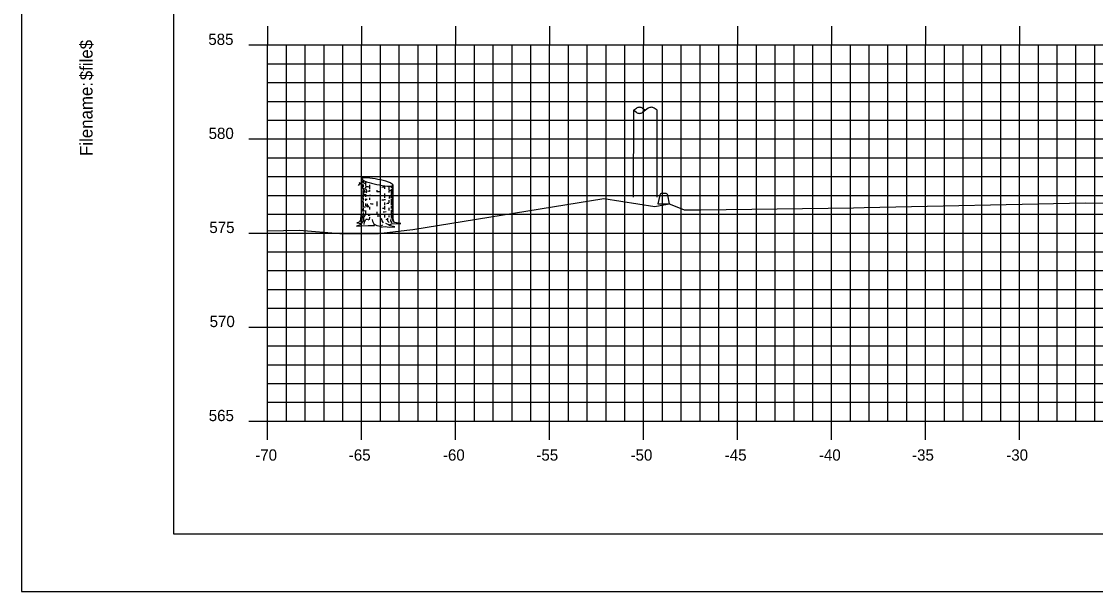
# Model space of a CAD drawing. Extents: x 1048343 to 1048513, y 781387 to 781497.
# Drawn here: x 1048343 to 1048400.2, y 781387.3 to 781417.6 of the extents above; entities that cross this region are included whole.
import ezdxf

# ---------------------------------------------------------------- set-up
doc = ezdxf.new("R2010")
doc.units = 0
for name, color, linetype in [('BORDER', 7, 'Continuous'), ('H_V ANNOTATION', 7, 'Continuous'), ('M_Trees_Conifer_Pay', 7, 'Continuous'), ('MAJOR', 7, 'Continuous'), ('MINOR', 7, 'Continuous'), ('PLOT BOUNDARY', 7, 'Continuous'), ('S_Curb_Type_3', 7, 'Continuous'), ('S_Roadway_Centerline', 7, 'Continuous'), ('S_Utilities_Pole_Power', 7, 'Continuous')]:
    doc.layers.add(name, color=color, linetype=linetype)

msp = doc.modelspace()

# ---------------------------------------------------------------- linework, layer by layer
at = {"layer": 'BORDER'}
msp.add_lwpolyline([(1048351.12, 781390.375), (1048511.12, 781390.375), (1048511.12, 781495.375), (1048351.12, 781495.375)], close=True, dxfattribs=at)
at = {"layer": 'M_Trees_Conifer_Pay'}
for p, q in [((1048361.128, 781407.614), (1048361.128, 781409.261)), ((1048361.2, 781409.188), (1048361.2, 781409.026)), ((1048361.2, 781408.958), (1048361.2, 781408.83)), ((1048361.317, 781409.127), (1048361.317, 781408.904)), ((1048361.317, 781408.816), (1048361.317, 781408.768)), ((1048361.546, 781408.931), (1048361.546, 781408.732)), ((1048362.342, 781408.889), (1048362.342, 781408.721)), ((1048362.562, 781408.869), (1048362.562, 781408.637)), ((1048362.687, 781408.877), (1048362.687, 781408.779)), ((1048362.745, 781408.888), (1048362.745, 781408.417)), ((1048362.792, 781407.203), (1048362.792, 781408.925)), ((1048361.2, 781408.643), (1048361.2, 781408.307)), ((1048361.2, 781408.27), (1048361.2, 781408.108)), ((1048361.26, 781408.633), (1048361.312, 781408.573)), ((1048361.317, 781408.433), (1048361.317, 781408.301)), ((1048361.317, 781408.19), (1048361.317, 781408.081)), ((1048361.546, 781408.674), (1048361.546, 781408.585)), ((1048361.546, 781408.238), (1048361.546, 781408.133)), ((1048361.936, 781408.658), (1048361.936, 781408.562)), ((1048362.342, 781408.484), (1048362.342, 781408.247)), ((1048362.562, 781408.596), (1048362.562, 781408.522)), ((1048362.687, 781408.705), (1048362.687, 781408.501)), ((1048362.687, 781408.443), (1048362.687, 781408.244)), ((1048362.687, 781408.196), (1048362.687, 781407.86)), ((1048362.745, 781408.352), (1048362.745, 781408.044)), ((1048361.2, 781408.06), (1048361.2, 781407.844)), ((1048361.2, 781407.813), (1048361.2, 781407.739)), ((1048361.2, 781407.698), (1048361.2, 781407.525)), ((1048361.317, 781407.945), (1048361.317, 781407.803)), ((1048361.546, 781407.766), (1048361.546, 781407.619)), ((1048361.936, 781408.044), (1048361.936, 781407.97)), ((1048361.936, 781407.945), (1048361.936, 781407.797)), ((1048362.342, 781408.003), (1048362.342, 781407.85)), ((1048362.342, 781407.807), (1048362.342, 781407.634)), ((1048362.562, 781408.118), (1048362.562, 781407.98)), ((1048362.562, 781407.708), (1048362.562, 781407.566)), ((1048362.687, 781407.807), (1048362.687, 781407.671)), ((1048362.745, 781407.997), (1048362.745, 781407.505)), ((1048361.317, 781407.576), (1048361.317, 781407.404)), ((1048361.546, 781407.387), (1048361.546, 781407.299)), ((1048361.936, 781407.505), (1048361.936, 781407.352)), ((1048362.342, 781407.356), (1048362.342, 781407.203)), ((1048362.562, 781407.305), (1048362.562, 781407.21)), ((1048362.687, 781407.572), (1048362.687, 781407.194)), ((1048362.745, 781407.451), (1048362.745, 781407.203)), ((1048362.124, 781406.746), (1048362.25, 781406.81)), ((1048362.562, 781406.81), (1048362.399, 781406.874))]:
    msp.add_line(p, q, dxfattribs=at)
for points in [[(1048361.083, 781408.992), (1048361.007, 781408.999), (1048360.935, 781408.9)], [(1048361.312, 781408.759), (1048361.275, 781408.684), (1048361.228, 781408.742), (1048361.17, 781408.81), (1048361.077, 781409.003), (1048361.013, 781409.051), (1048360.982, 781409.057)], [(1048361.297, 781408.505), (1048361.26, 781408.633), (1048361.197, 781408.748), (1048361.166, 781408.816), (1048361.097, 781408.962)], [(1048361.345, 781408.721), (1048361.376, 781408.637), (1048361.38, 781408.569), (1048361.349, 781408.505)], [(1048362.613, 781408.231), (1048362.619, 781408.326), (1048362.576, 781408.303), (1048362.576, 781408.209)], [(1048361.128, 781407.614), (1048361.077, 781407.352), (1048361.061, 781407.078), (1048361.003, 781406.953), (1048360.867, 781406.922), (1048361.098, 781406.885), (1048361.098, 781406.885), (1048361.092, 781406.837), (1048360.844, 781406.743), (1048361.119, 781406.759), (1048361.474, 781406.78), (1048361.796, 781406.769), (1048361.789, 781406.852), (1048361.937, 781406.769), (1048362.124, 781406.746), (1048362.1, 781406.679), (1048362.368, 781406.722), (1048362.588, 781406.695), (1048362.881, 781406.712), (1048362.592, 781406.769), (1048362.562, 781406.81), (1048362.724, 781406.868), (1048362.961, 781406.879), (1048363.202, 781406.879), (1048362.86, 781406.936), (1048362.819, 781407.016), (1048362.792, 781407.203)], [(1048361.474, 781407.832), (1048361.462, 781407.755), (1048361.415, 781407.766), (1048361.427, 781407.932)], [(1048361.302, 781407.326), (1048361.228, 781407.221), (1048361.223, 781407.047), (1048361.098, 781406.885)], [(1048361.203, 781407.471), (1048361.197, 781407.326), (1048361.149, 781407.257), (1048361.139, 781407.058)], [(1048361.26, 781406.831), (1048361.275, 781406.969), (1048361.349, 781407.098)], [(1048361.539, 781407.221), (1048361.528, 781407.095), (1048361.454, 781407.051)], [(1048361.789, 781406.852), (1048361.715, 781406.994), (1048361.705, 781407.095)], [(1048362.277, 781406.922), (1048362.21, 781407.016), (1048362.183, 781407.156)], [(1048362.504, 781407.163), (1048362.504, 781407.031), (1048362.592, 781406.932)], [(1048362.666, 781407.136), (1048362.661, 781407.02), (1048362.714, 781406.932), (1048362.724, 781406.868)], [(1048362.745, 781407.156), (1048362.766, 781407.078), (1048362.786, 781406.984)]]:
    msp.add_lwpolyline(points, dxfattribs=at)
for centre, radius, start, end in [((1048361.151, 781409.261), 0.0226, 168.2806, 179.9685), ((1048361.155, 781409.261), 0.0264, 179.9685, 190.7806), ((1048361.162, 781409.134), 0.0334, 185.7849, 196.0515), ((1048361.162, 781408.98), 0.0334, 185.7849, 196.0515), ((1048361.151, 781409.261), 0.0226, 156.5926, 168.2806), ((1048361.16, 781409.262), 0.0314, 190.7806, 203.4842), ((1048361.172, 781409.137), 0.0441, 196.0515, 210), ((1048361.172, 781408.983), 0.0441, 196.0515, 210), ((1048361.154, 781409.259), 0.0264, 145.7806, 156.5926), ((1048361.179, 781409.27), 0.0527, 203.4842, 213.2806), ((1048361.159, 781409.256), 0.0314, 133.077, 145.7806), ((1048361.188, 781409.146), 0.0624, 210, 228.7494), ((1048361.188, 781408.992), 0.0624, 210, 228.7494), ((1048361.203, 781409.286), 0.0817, 213.2806, 227.6113), ((1048361.173, 781409.241), 0.0527, 123.2806, 133.077), ((1048361.189, 781409.217), 0.0817, 108.9499, 123.2806), ((1048361.26, 781409.229), 0.172, 228.7494, 240), ((1048361.26, 781409.075), 0.172, 228.7494, 240), ((1048361.317, 781409.411), 0.251, 227.6113, 235.7806), ((1048361.244, 781409.057), 0.251, 100.7806, 108.9499), ((1048361.459, 781409.42), 0.571, 240, 242.9763), ((1048361.627, 781409.866), 0.802, 235.7806, 251.9406), ((1048361.347, 781408.516), 0.802, 84.6206, 100.7806), ((1048361.459, 781409.574), 0.571, 247.5868, 255.5683), ((1048361.459, 781409.42), 0.571, 255.6333, 261.8968), ((1048362.984, 781414.028), 5.179, 251.9406, 258.2806), ((1048361.96, 781412.937), 4.124, 261.8968, 263.762), ((1048360.937, 781404.158), 5.179, 78.2806, 84.6206), ((1048362.984, 781414.028), 5.179, 258.2806, 264.6206), ((1048360.937, 781404.158), 5.179, 71.9406, 78.2806), ((1048361.96, 781412.937), 4.124, 273.2669, 275.3045), ((1048362.574, 781409.67), 0.802, 264.6206, 280.7806), ((1048362.294, 781408.319), 0.802, 55.7806, 71.9406), ((1048362.677, 781409.129), 0.251, 280.7806, 288.9499), ((1048362.603, 781408.775), 0.251, 47.6113, 55.7806), ((1048362.732, 781408.969), 0.0817, 288.9499, 303.2806), ((1048362.717, 781408.9), 0.0817, 33.2806, 47.6113), ((1048362.748, 781408.945), 0.0527, 303.2806, 313.077), ((1048362.762, 781408.929), 0.0314, 313.077, 325.7806), ((1048362.741, 781408.916), 0.0527, 23.4842, 33.2806), ((1048362.766, 781408.926), 0.0264, 325.7806, 336.5926), ((1048362.761, 781408.924), 0.0314, 10.7806, 23.4842), ((1048362.77, 781408.925), 0.0226, 336.5926, 348.2806), ((1048362.766, 781408.925), 0.0264, 359.9685, 10.7806), ((1048362.77, 781408.925), 0.0226, 348.2806, 359.9685), ((1048362.76, 781408.747), 0.0334, 0, 16.0515), ((1048361.162, 781408.536), 0.0334, 185.7849, 196.0515), ((1048361.163, 781408.3), 0.0334, 185.7849, 196.0515), ((1048361.173, 781408.303), 0.0441, 196.0515, 210), ((1048361.189, 781408.312), 0.0624, 210, 228.7494), ((1048361.262, 781408.395), 0.172, 228.7494, 240), ((1048361.461, 781408.74), 0.571, 240, 242.8104), ((1048361.46, 781408.976), 0.571, 242.9571, 255.5507), ((1048361.461, 781408.74), 0.571, 253.0704, 261.8968), ((1048361.962, 781412.704), 4.124, 262.9442, 264.2151), ((1048361.96, 781412.493), 4.124, 264.0496, 266.2948), ((1048361.962, 781412.704), 4.124, 269.6419, 270), ((1048361.962, 781412.704), 4.124, 270, 271.9249), ((1048362.462, 781409.187), 0.571, 282.0154, 293.1403), ((1048362.461, 781408.976), 0.571, 292.9413, 300), ((1048362.462, 781409.187), 0.571, 299.6633, 300), ((1048362.462, 781408.74), 0.571, 299.6633, 300), ((1048362.662, 781408.842), 0.172, 300, 311.2506), ((1048362.662, 781408.395), 0.172, 300, 311.2506), ((1048362.734, 781408.759), 0.0624, 311.2506, 330), ((1048362.734, 781408.312), 0.0624, 311.2506, 330), ((1048362.75, 781408.75), 0.0441, 330, 343.9485), ((1048362.75, 781408.303), 0.0441, 330, 343.9485), ((1048362.76, 781408.747), 0.0334, 343.9485, 360), ((1048362.76, 781408.3), 0.0334, 0, 16.0515), ((1048362.76, 781408.3), 0.0334, 343.9485, 360), ((1048361.163, 781408.09), 0.0334, 185.7849, 196.0515), ((1048361.163, 781407.656), 0.0334, 185.7849, 196.0515), ((1048361.173, 781408.093), 0.0441, 196.0515, 210), ((1048361.173, 781407.659), 0.0441, 196.0515, 210), ((1048361.189, 781408.102), 0.0624, 210, 228.7494), ((1048361.189, 781407.668), 0.0624, 210, 228.7494), ((1048361.262, 781408.185), 0.172, 228.7494, 240), ((1048361.262, 781407.75), 0.172, 228.7494, 240), ((1048361.461, 781408.53), 0.571, 240, 242.8104), ((1048361.461, 781408.293), 0.571, 242.8104, 254.6017), ((1048361.962, 781412.258), 4.124, 261.8968, 262.3875), ((1048361.962, 781412.048), 4.124, 264.5431, 266.8507), ((1048361.962, 781412.048), 4.124, 269.6419, 270), ((1048361.962, 781412.258), 4.124, 273.3324, 275.919), ((1048361.962, 781411.811), 4.124, 273.6807, 275.284), ((1048361.962, 781412.048), 4.124, 276.8526, 278.1032), ((1048362.462, 781408.53), 0.571, 278.1032, 280.7293), ((1048362.462, 781408.53), 0.571, 293.1403, 300), ((1048362.462, 781408.293), 0.571, 293.1403, 300), ((1048362.662, 781408.185), 0.172, 300, 311.2506), ((1048362.662, 781407.948), 0.172, 300, 311.2506), ((1048362.734, 781408.102), 0.0624, 311.2506, 330), ((1048362.734, 781407.866), 0.0624, 311.2506, 330), ((1048362.75, 781408.093), 0.0441, 330, 343.9485), ((1048362.75, 781407.856), 0.0441, 330, 343.9485), ((1048362.76, 781408.09), 0.0334, 0, 16.0515), ((1048362.76, 781408.09), 0.0334, 343.9485, 360), ((1048362.76, 781407.853), 0.0334, 0, 16.0515), ((1048362.76, 781407.853), 0.0334, 343.9485, 360), ((1048362.76, 781407.656), 0.0334, 0, 16.0515), ((1048361.163, 781407.24), 0.0334, 185.7849, 196.0515), ((1048361.173, 781407.243), 0.0441, 196.0515, 210), ((1048361.189, 781407.252), 0.0624, 210, 228.7494), ((1048361.262, 781407.335), 0.172, 228.7494, 240), ((1048361.461, 781408.096), 0.571, 240, 250.7093), ((1048361.461, 781407.9), 0.571, 242.7279, 251.4933), ((1048361.461, 781407.68), 0.571, 258.363, 261.8968), ((1048361.962, 781411.197), 4.124, 261.8968, 262.6316), ((1048361.962, 781411.417), 4.124, 263.2104, 264.2151), ((1048361.962, 781411.417), 4.124, 269.8672, 270), ((1048361.962, 781411.417), 4.124, 270, 272.1883), ((1048361.962, 781411.613), 4.124, 274.1603, 276.5009), ((1048361.962, 781411.197), 4.124, 276.488, 277.5562), ((1048362.473, 781408.102), 0.571, 291.9732, 298.7631), ((1048362.462, 781407.9), 0.571, 293.1403, 300), ((1048362.462, 781407.68), 0.571, 295.4686, 300), ((1048362.662, 781407.555), 0.172, 300, 311.2506), ((1048362.662, 781407.335), 0.172, 300, 311.2506), ((1048362.734, 781407.472), 0.0624, 311.2506, 330), ((1048362.734, 781407.252), 0.0624, 311.2506, 330), ((1048362.75, 781407.463), 0.0441, 330, 343.9485), ((1048362.75, 781407.243), 0.0441, 330, 343.9485), ((1048362.76, 781407.46), 0.0334, 0, 16.0515), ((1048362.76, 781407.46), 0.0334, 343.9485, 360), ((1048362.76, 781407.24), 0.0334, 0, 16.0515), ((1048362.76, 781407.24), 0.0334, 343.9485, 360)]:
    msp.add_arc(centre, radius, start, end, dxfattribs=at)
at = {"layer": 'MAJOR'}
for p, q in [((1048356.119, 781417.377), (1048356.119, 781416.375)), ((1048361.119, 781417.377), (1048361.119, 781416.375)), ((1048366.119, 781417.377), (1048366.119, 781416.375)), ((1048371.119, 781417.377), (1048371.119, 781416.375)), ((1048376.119, 781417.377), (1048376.119, 781416.375)), ((1048381.119, 781417.377), (1048381.119, 781416.375)), ((1048386.119, 781417.377), (1048386.119, 781416.375)), ((1048391.119, 781417.377), (1048391.119, 781416.375)), ((1048396.119, 781417.377), (1048396.119, 781416.375)), ((1048355.117, 781416.375), (1048356.119, 781416.375)), ((1048356.119, 781416.375), (1048496.119, 781416.375)), ((1048356.119, 781396.375), (1048356.119, 781416.375)), ((1048356.119, 781396.375), (1048356.119, 781416.375)), ((1048356.119, 781416.375), (1048496.119, 781416.375)), ((1048361.119, 781396.375), (1048361.119, 781416.375)), ((1048366.119, 781396.375), (1048366.119, 781416.375)), ((1048371.119, 781396.375), (1048371.119, 781416.375)), ((1048376.119, 781396.375), (1048376.119, 781416.375)), ((1048381.119, 781396.375), (1048381.119, 781416.375)), ((1048386.119, 781396.375), (1048386.119, 781416.375)), ((1048391.119, 781396.375), (1048391.119, 781416.375)), ((1048396.119, 781396.375), (1048396.119, 781416.375)), ((1048355.117, 781411.375), (1048356.119, 781411.375)), ((1048356.119, 781411.375), (1048496.119, 781411.375)), ((1048355.117, 781406.375), (1048356.119, 781406.375)), ((1048356.119, 781406.375), (1048496.119, 781406.375)), ((1048355.117, 781401.375), (1048356.119, 781401.375)), ((1048356.119, 781401.375), (1048496.119, 781401.375)), ((1048355.117, 781396.375), (1048356.119, 781396.375)), ((1048356.119, 781396.375), (1048496.119, 781396.375)), ((1048356.119, 781396.375), (1048496.119, 781396.375)), ((1048356.119, 781395.373), (1048356.119, 781396.375)), ((1048361.119, 781395.373), (1048361.119, 781396.375)), ((1048366.119, 781395.373), (1048366.119, 781396.375)), ((1048371.119, 781395.373), (1048371.119, 781396.375)), ((1048376.119, 781395.373), (1048376.119, 781396.375)), ((1048381.119, 781395.373), (1048381.119, 781396.375)), ((1048386.119, 781395.373), (1048386.119, 781396.375)), ((1048391.119, 781395.373), (1048391.119, 781396.375)), ((1048396.119, 781395.373), (1048396.119, 781396.375))]:
    msp.add_line(p, q, dxfattribs=at)
at = {"layer": 'MINOR'}
for p, q in [((1048357.119, 781396.375), (1048357.119, 781416.375)), ((1048358.119, 781396.375), (1048358.119, 781416.375)), ((1048359.119, 781396.375), (1048359.119, 781416.375)), ((1048360.119, 781396.375), (1048360.119, 781416.375)), ((1048362.119, 781396.375), (1048362.119, 781416.375)), ((1048363.119, 781396.375), (1048363.119, 781416.375)), ((1048364.119, 781396.375), (1048364.119, 781416.375)), ((1048365.119, 781396.375), (1048365.119, 781416.375)), ((1048367.119, 781396.375), (1048367.119, 781416.375)), ((1048368.119, 781396.375), (1048368.119, 781416.375)), ((1048369.119, 781396.375), (1048369.119, 781416.375)), ((1048370.119, 781396.375), (1048370.119, 781416.375)), ((1048372.119, 781396.375), (1048372.119, 781416.375)), ((1048373.119, 781396.375), (1048373.119, 781416.375)), ((1048374.119, 781396.375), (1048374.119, 781416.375)), ((1048375.119, 781396.375), (1048375.119, 781416.375)), ((1048377.119, 781396.375), (1048377.119, 781416.375)), ((1048378.119, 781396.375), (1048378.119, 781416.375)), ((1048379.119, 781396.375), (1048379.119, 781416.375)), ((1048380.119, 781396.375), (1048380.119, 781416.375)), ((1048382.119, 781396.375), (1048382.119, 781416.375)), ((1048383.119, 781396.375), (1048383.119, 781416.375)), ((1048384.119, 781396.375), (1048384.119, 781416.375)), ((1048385.119, 781396.375), (1048385.119, 781416.375)), ((1048387.119, 781396.375), (1048387.119, 781416.375)), ((1048388.119, 781396.375), (1048388.119, 781416.375)), ((1048389.119, 781396.375), (1048389.119, 781416.375)), ((1048390.119, 781396.375), (1048390.119, 781416.375)), ((1048392.119, 781396.375), (1048392.119, 781416.375)), ((1048393.119, 781396.375), (1048393.119, 781416.375)), ((1048394.119, 781396.375), (1048394.119, 781416.375)), ((1048395.119, 781396.375), (1048395.119, 781416.375)), ((1048397.119, 781396.375), (1048397.119, 781416.375)), ((1048398.119, 781396.375), (1048398.119, 781416.375)), ((1048399.119, 781396.375), (1048399.119, 781416.375)), ((1048400.119, 781396.375), (1048400.119, 781416.375)), ((1048356.119, 781415.375), (1048496.119, 781415.375)), ((1048356.119, 781415.375), (1048357.121, 781415.375)), ((1048356.119, 781414.375), (1048496.119, 781414.375)), ((1048356.119, 781414.375), (1048357.121, 781414.375)), ((1048356.119, 781413.375), (1048496.119, 781413.375)), ((1048356.119, 781413.375), (1048357.121, 781413.375)), ((1048356.119, 781412.375), (1048496.119, 781412.375)), ((1048356.119, 781412.375), (1048357.121, 781412.375)), ((1048356.119, 781410.375), (1048496.119, 781410.375)), ((1048356.119, 781410.375), (1048357.121, 781410.375)), ((1048356.119, 781409.375), (1048496.119, 781409.375)), ((1048356.119, 781409.375), (1048357.121, 781409.375)), ((1048356.119, 781408.375), (1048496.119, 781408.375)), ((1048356.119, 781408.375), (1048357.121, 781408.375)), ((1048356.119, 781407.375), (1048496.119, 781407.375)), ((1048356.119, 781407.375), (1048357.121, 781407.375)), ((1048356.119, 781405.375), (1048496.119, 781405.375)), ((1048356.119, 781405.375), (1048357.121, 781405.375)), ((1048356.119, 781404.375), (1048496.119, 781404.375)), ((1048356.119, 781404.375), (1048357.121, 781404.375)), ((1048356.119, 781403.375), (1048496.119, 781403.375)), ((1048356.119, 781403.375), (1048357.121, 781403.375)), ((1048356.119, 781402.375), (1048496.119, 781402.375)), ((1048356.119, 781402.375), (1048357.121, 781402.375)), ((1048356.119, 781400.375), (1048496.119, 781400.375)), ((1048356.119, 781400.375), (1048357.121, 781400.375)), ((1048356.119, 781399.375), (1048496.119, 781399.375)), ((1048356.119, 781399.375), (1048357.121, 781399.375)), ((1048356.119, 781398.375), (1048496.119, 781398.375)), ((1048356.119, 781398.375), (1048357.121, 781398.375)), ((1048356.119, 781397.375), (1048496.119, 781397.375)), ((1048356.119, 781397.375), (1048357.121, 781397.375))]:
    msp.add_line(p, q, dxfattribs=at)
at = {"layer": 'PLOT BOUNDARY'}
msp.add_lwpolyline([(1048343.026, 781387.316), (1048513.026, 781387.316), (1048513.026, 781497.316), (1048343.026, 781497.316)], close=True, dxfattribs=at)
at = {"layer": 'S_Curb_Type_3'}
for points in [[(1048376.981, 781408.381), (1048376.878, 781407.936), (1048377.503, 781407.936), (1048377.401, 781408.381)], [(1048377.279, 781408.478), (1048377.103, 781408.478)]]:
    msp.add_lwpolyline(points, dxfattribs=at)
for centre, start, end in [((1048377.103, 781408.353), 90, 167.0054), ((1048377.279, 781408.353), 12.9946, 90)]:
    msp.add_arc(centre, 0.125, start, end, dxfattribs=at)
at = {"layer": 'S_Roadway_Centerline'}
msp.add_lwpolyline([(1048356.119, 781406.487), (1048357.811, 781406.531), (1048359.958, 781406.346), (1048362.011, 781406.356), (1048363.692, 781406.553), (1048363.846, 781406.555), (1048374.007, 781408.207), (1048376.725, 781407.792), (1048377.397, 781407.918), (1048377.503, 781407.936), (1048377.534, 781407.902), (1048378.276, 781407.603), (1048378.279, 781407.605), (1048379.156, 781407.616), (1048387.292, 781407.713), (1048387.853, 781407.729), (1048399.613, 781407.977), (1048402.647, 781407.956)], dxfattribs=at)
at = {"layer": 'S_Utilities_Pole_Power'}
for p, q in [((1048375.587, 781412.899), (1048375.743, 781413.009)), ((1048375.587, 781408.279), (1048375.591, 781412.899)), ((1048375.743, 781412.788), (1048375.587, 781412.899)), ((1048376.056, 781413.009), (1048376.213, 781412.899)), ((1048376.213, 781412.899), (1048376.056, 781412.788)), ((1048376.369, 781413.009), (1048376.213, 781412.899)), ((1048376.837, 781412.899), (1048376.681, 781413.009)), ((1048376.837, 781408.279), (1048376.841, 781412.899))]:
    msp.add_line(p, q, dxfattribs=at)
for centre, start, end in [((1048375.9, 781412.788), 90, 125.2644), ((1048375.9, 781413.009), 234.7356, 270), ((1048375.9, 781412.788), 54.7356, 90), ((1048375.9, 781413.009), 270, 305.2644), ((1048376.525, 781412.788), 90, 125.2644), ((1048376.525, 781412.788), 54.7356, 90)]:
    msp.add_arc(centre, 0.271, start, end, dxfattribs=at)

# ---------------------------------------------------------------- texts
at = {"layer": 'BORDER'}
for s, p in [('$file$', (1048346.805, 781414.501)), ('Filename:', (1048346.805, 781410.474))]:
    msp.add_text(s, height=0.6696, rotation=90, dxfattribs=at).set_placement(p)
at = {"layer": 'H_V ANNOTATION'}
for s, p in [('585', (1048352.965, 781416.375)), ('580', (1048352.981, 781411.375)), ('575', (1048353.019, 781406.375)), ('570', (1048353.035, 781401.375)), ('565', (1048352.987, 781396.375)), ('-70', (1048355.461, 781394.275)), ('-65', (1048360.437, 781394.275)), ('-60', (1048365.445, 781394.275)), ('-55', (1048370.416, 781394.275)), ('-50', (1048375.424, 781394.275)), ('-45', (1048380.437, 781394.275)), ('-40', (1048385.445, 781394.275)), ('-35', (1048390.4, 781394.275)), ('-30', (1048395.408, 781394.275))]:
    msp.add_text(s, height=0.6, dxfattribs=at).set_placement(p)
at = {"layer": 'MAJOR'}
msp.add_text('-', height=0.006, dxfattribs=at).set_placement((1048356.115, 781396.375))
at = {"layer": 'S_Roadway_Centerline'}
for s, p in [('L', (1048399.604, 781407.97)), ('C', (1048399.607, 781407.977))]:
    msp.add_text(s, height=0.0146, dxfattribs=at).set_placement(p)

doc.saveas('drawing.dxf')
